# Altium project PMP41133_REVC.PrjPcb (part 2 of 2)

## Sheet PMP41133_RevC_Hardware.SchDoc
size 431 x 279 mm; Date: Not shown in title block; ApprovedBy: Not shown in title block; CheckedBy: Not shown in title block; Author: Not shown in title block; CompanyName: Not shown in title block; Engineer: Not shown in title block; Organization: Not shown in title block; Address1: Not shown in title block; Address2: Not shown in title block; Address3: Not shown in title block; Address4: Not shown in title block; DocumentNumber: 3; Revision: Use project parameter SCH_Rev; SheetNumber: 3; SheetTotal: 3; PageSetup: Record=PageOptions¦CenterHorizontal=True¦CenterVertical=True¦PrintScale=1.00¦XCorrection=1.00¦YCorrection=1.00¦PrintKind=0¦BorderSize=5000000¦LeftOffset=0¦BottomOffset=0¦Orientation=2¦PaperLength=1000¦PaperWidth=1000¦Scale=100¦PaperSource=15¦PrintQuality=600¦MediaType=1¦DitherType=10¦PaperKind=Letter¦PrintScaleMode=1
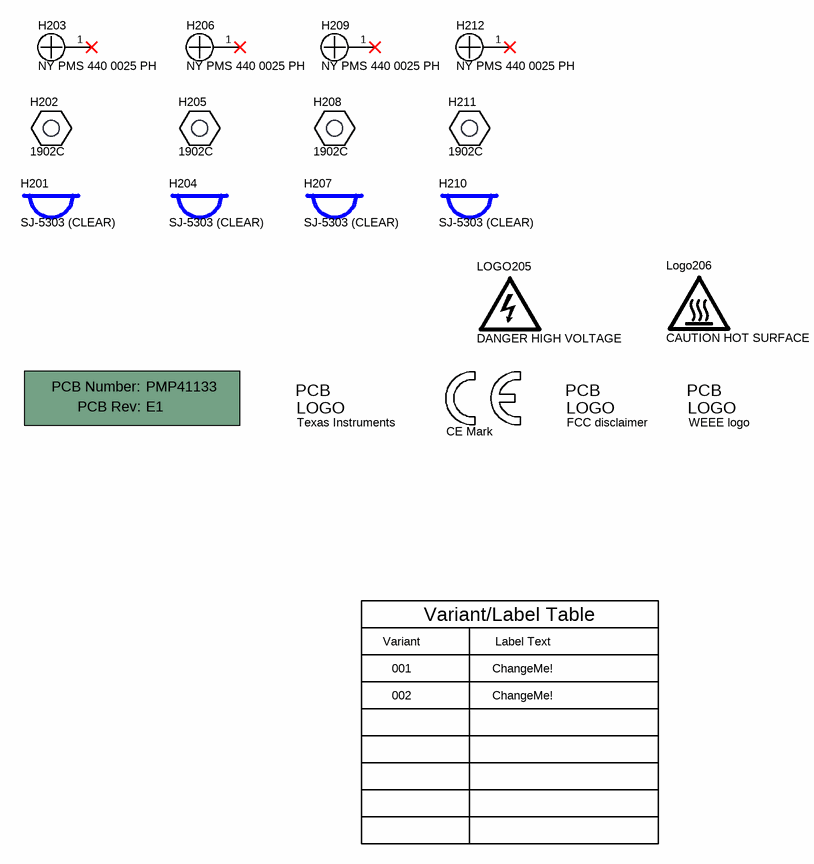
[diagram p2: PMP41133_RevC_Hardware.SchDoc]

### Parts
!PCB201  Printed Circuit Board  (value not drawn)  (mechanical)
H201  SJ-5303 (CLEAR)  [Bumpon_SJ5003Transparent]
H202  1902C  [Keystone_1902C]
H203  NY PMS 440 0025 PH  [NY PMS 440 0025 PH]
H204  SJ-5303 (CLEAR)  [Bumpon_SJ5003Transparent]
H205  1902C  [Keystone_1902C]
H206  NY PMS 440 0025 PH  [NY PMS 440 0025 PH]
H207  SJ-5303 (CLEAR)  [Bumpon_SJ5003Transparent]
H208  1902C  [Keystone_1902C]
H209  NY PMS 440 0025 PH  [NY PMS 440 0025 PH]
H210  SJ-5303 (CLEAR)  [Bumpon_SJ5003Transparent]
H211  1902C  [Keystone_1902C]
H212  NY PMS 440 0025 PH  [NY PMS 440 0025 PH]
Logo201  Texas Instruments  [TI_Stacked_Overlay_Small]  (no BOM)
Logo202  CE Mark  [CE_Mark_5mm]  (no BOM)
Logo203  FCC disclaimer  [FCC_disclaimer]  (no BOM)
Logo204  WEEE logo  [WEEE_Minimum]  (no BOM)
LOGO205  DANGER HIGH VOLTAGE  [IEC_HighVoltage_Small]  (no BOM)
Logo206  CAUTION HOT SURFACE  [IEC_HotSurface_Small]  (no BOM)

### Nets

Not connected (* = marked no-connect by the designer): H203 1*; H206 1*; H209 1*; H212 1*

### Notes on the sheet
- Variant
- Variant/Label Table
- Label Text
- 001
- 002
- ChangeMe!

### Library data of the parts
!PCB201 = CMP-0003618-2: Manufacturer: Any; PartNumber: PMP41133
H201 H204 H207 H210 = CMP-0003620-1: Bumpon, Hemisphere, 0.44 X 0.20, Clear; Manufacturer: 3M
H202 H205 H208 H211 = CMP-0003610-1: Standoff, Hex, 0.5"L #4-40 Nylon; Manufacturer: Keystone; CompType: Hardware
H203 H206 H209 H212 = CMP-0003617-1: Machine Screw, Round, #4-40 x 1/4, Nylon, Philips panhead; Manufacturer: B&F Fastener Supply; CompType: Hardware
Logo201 = CMP-0074838-1: Texas Instrument Corporate Signature; SymbolCreator: a0412235; Lib Reference: TI_Logo; Library Reference: Logo
Logo202 = CMP-0074844-1: SymbolCreator: a0412235
Logo203 = CMP-0074847-1: FCC_disclaimer; Library Reference: Logo
Logo204 = CMP-0074769-1
LOGO205 = CMP-0074835-1: IEC 61010-1 High Voltage Warning; SymbolCreator: a0412235
Logo206 = CMP-0074837-2: IEC 61010-1 Hot Surface Warning; Manufacturer: Texas Instruments; CompType: IC; AEC Category: Q200; SymbolCreator: a0412235

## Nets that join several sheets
PGND: PMP41133_RevC_Power Stage (29 pins), PMP41133_RevC_Controller (25 pins)
5VP: PMP41133_RevC_Power Stage (R13.2 R15.2), PMP41133_RevC_Controller (7 pins)
FB: PMP41133_RevC_Power Stage (C9.1 C29.1 Q6.4 R15.1), PMP41133_RevC_Controller (U101.5)
HO: PMP41133_RevC_Power Stage (R6.1), PMP41133_RevC_Controller (U102.6)
HO_OFF: PMP41133_RevC_Power Stage (R7.1), PMP41133_RevC_Controller (U102.7)
HS: PMP41133_RevC_Power Stage (9 pins), PMP41133_RevC_Controller (C112.1 C114.1 D110.1 U102.8)
ISNS: PMP41133_RevC_Power Stage (C6.2 C7.1 ISNS.1 R11.2), PMP41133_RevC_Controller (U101.9)
LO: PMP41133_RevC_Power Stage (D1.1 R5.1), PMP41133_RevC_Controller (U101.11)
VB: PMP41133_RevC_Power Stage (R12.1 VCC.1), PMP41133_RevC_Controller (5 pins)
VIN: PMP41133_RevC_Power Stage (11 pins), PMP41133_RevC_Controller (C101.2 Q102.3 R123.2 R127.2)

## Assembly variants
001: not fitted C13 C14 C16 C101 C102 D105 D106 D113 Q5 Q101 Q103 R13 R18 R22 R24 R102 R103 R105 R106 R108 R109 R126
